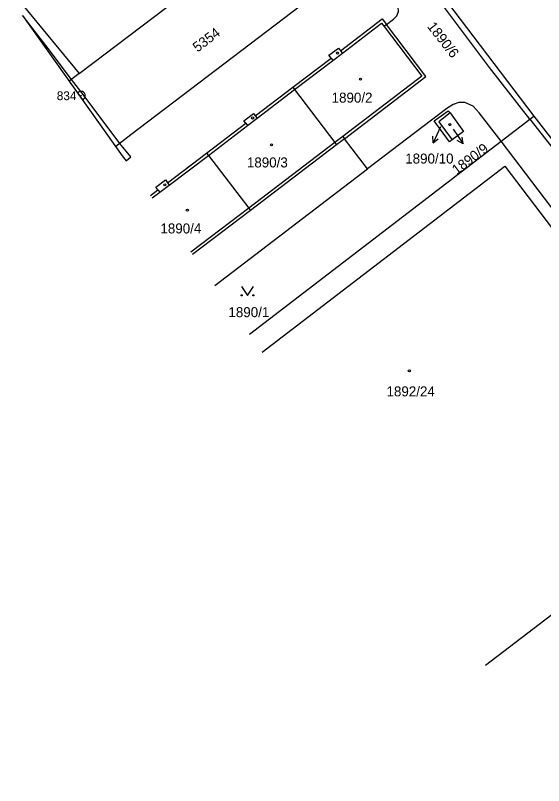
# Model space of a CAD drawing. Extents: x -821458 to -820266, y -1071458 to -1069826.
# Drawn here: x -821179.5 to -821089.7, y -1070873.1 to -1070742.2 of the extents above; entities that cross this region are included whole.
import ezdxf

# ---------------------------------------------------------------- set-up
doc = ezdxf.new("R2010")
doc.units = 0
for name, color, linetype in [('Vrstva 1', 7, 'Continuous'), ('Vrstva 13', 7, 'Continuous'), ('Vrstva 2', 7, 'Continuous'), ('Vrstva 3', 7, 'Continuous'), ('Vrstva 4', 7, 'Continuous'), ('Vrstva 5', 7, 'Continuous'), ('Vrstva 7', 7, 'Continuous'), ('Vrstva 8', 7, 'Continuous')]:
    doc.layers.add(name, color=color, linetype=linetype)

msp = doc.modelspace()

# ---------------------------------------------------------------- linework, layer by layer
at = {"layer": 'Vrstva 1'}
for p, q in [((-821168.67, -1070752.05), (-821145.53, -1070734.38)), ((-821179.52, -1070738.86), (-821168.67, -1070752.05)), ((-821168.67, -1070752.05), (-821170.38, -1070753.35)), ((-821096.91, -1070763.55), (-821092, -1070759.79)), ((-821092, -1070759.79), (-821091.35, -1070759.29)), ((-821091.35, -1070759.29), (-821086.06, -1070766.13)), ((-821139.72, -1070796.38), (-821096.91, -1070763.55)), ((-821123.55, -1070763.13), (-821124.88, -1070764.15)), ((-821124.88, -1070764.15), (-821139.54, -1070775.33)), ((-821139.54, -1070775.33), (-821149.39, -1070782.81))]:
    msp.add_line(p, q, dxfattribs=at)
for points in [[(-821057.85, -1070693.73), (-821110.68, -1070733.79), (-821091.35, -1070759.29)], [(-821092, -1070759.79), (-821098.88, -1070751), (-821112.32, -1070733.05), (-821111.78, -1070731.94), (-821111.85, -1070725.85)], [(-821123.75, -1070734.96), (-821159.87, -1070762.46), (-821162.46, -1070764.47)], [(-821116.4, -1070743.73), (-821115.21, -1070742.81), (-821114.66, -1070742.24), (-821114.37, -1070741.52), (-821114.39, -1070740.71), (-821114.75, -1070739.99), (-821116.84, -1070737.34), (-821123.75, -1070734.96)], [(-821132.34, -1070754.36), (-821125.83, -1070749.4), (-821126.18, -1070748.92), (-821124.56, -1070747.71), (-821124.2, -1070748.16), (-821117.15, -1070742.75), (-821116.4, -1070743.73)], [(-821123.55, -1070763.13), (-821109.68, -1070752.54), (-821116.4, -1070743.73)], [(-821147, -1070765.57), (-821140.34, -1070760.48), (-821140.68, -1070760.06), (-821139.04, -1070758.81), (-821138.72, -1070759.23), (-821132.34, -1070754.36)], [(-821132.34, -1070754.36), (-821132.03, -1070754.76), (-821125.19, -1070763.75), (-821124.88, -1070764.15)], [(-821096.91, -1070763.55), (-821100.61, -1070758.7), (-821101.64, -1070757.58), (-821103.05, -1070756.97), (-821104.08, -1070756.98), (-821105.06, -1070757.3), (-821106.12, -1070757.97), (-821119.65, -1070768.24), (-821123.55, -1070763.13)], [(-821105.24, -1070763.34), (-821105.67, -1070763.63), (-821108.27, -1070760.09), (-821105.91, -1070758.36), (-821105.57, -1070758.75)], [(-821105.57, -1070758.75), (-821107.48, -1070760.26), (-821105.24, -1070763.34)], [(-821105.57, -1070758.75), (-821103.27, -1070761.88), (-821105.24, -1070763.34)], [(-821085.02, -1070873.12), (-821066.67, -1070861.23), (-821045.28, -1070847.39), (-821043.79, -1070846.02), (-821042.61, -1070844.38), (-821041.71, -1070842.48), (-821041.39, -1070840.53), (-821041.49, -1070838.54), (-821041.98, -1070836.55), (-821042.62, -1070835.15), (-821043.18, -1070834.17), (-821055.9, -1070817.47), (-821096.91, -1070763.55)], [(-821156.52, -1070772.79), (-821155.27, -1070771.84), (-821155.65, -1070771.34), (-821154.01, -1070770.13), (-821153.64, -1070770.6), (-821147, -1070765.57)], [(-821147, -1070765.57), (-821146.7, -1070765.96), (-821139.84, -1070774.93), (-821139.54, -1070775.33)], [(-821137.57, -1070799.4), (-821096.27, -1070767.81), (-821077.16, -1070792.93), (-821076.94, -1070793.21), (-821084.09, -1070798.68), (-821081.35, -1070802.28), (-821074.19, -1070796.85), (-821056.57, -1070819.88), (-821099.56, -1070852.72)]]:
    msp.add_lwpolyline(points, dxfattribs=at)
at = {"layer": 'Vrstva 13'}
msp.add_line((-821178.33, -1070742.19), (-821161.35, -1070766.02), dxfattribs=at)
msp.add_lwpolyline([(-821161.35, -1070766.02), (-821160.67, -1070766.86), (-821159.91, -1070766.21), (-821161.76, -1070763.93), (-821167.98, -1070755.62), (-821169.98, -1070753.05), (-821173.97, -1070747.81), (-821178.05, -1070742.52), (-821178.33, -1070742.19)], dxfattribs=at)
at = {"layer": 'Vrstva 3'}
msp.add_lwpolyline([(-821141.04, -1070788.26), (-821140.04, -1070789.76), (-821139.04, -1070788.26)], dxfattribs=at)
for centre in [(-821141.04, -1070789.76), (-821139.04, -1070789.76)]:
    msp.add_circle(centre, 0.1, dxfattribs=at)
at = {"layer": 'Vrstva 4'}
for p, q in [((-821123.89, -1070748.55), (-821117.23, -1070743.48)), ((-821117.23, -1070743.48), (-821116.81, -1070744.04)), ((-821116.4, -1070743.73), (-821116.81, -1070744.04)), ((-821116.81, -1070744.04), (-821110.39, -1070752.47)), ((-821124.2, -1070748.16), (-821123.89, -1070748.55)), ((-821125.83, -1070749.4), (-821125.53, -1070749.81)), ((-821125.53, -1070749.81), (-821123.89, -1070748.55)), ((-821132.03, -1070754.76), (-821125.53, -1070749.81)), ((-821110.39, -1070752.47), (-821123.85, -1070762.73)), ((-821138.41, -1070759.63), (-821132.03, -1070754.76)), ((-821140.03, -1070760.87), (-821138.41, -1070759.63)), ((-821138.72, -1070759.23), (-821138.41, -1070759.63)), ((-821092, -1070759.79), (-821064.25, -1070795.28)), ((-821146.7, -1070765.96), (-821140.03, -1070760.87)), ((-821140.34, -1070760.48), (-821140.03, -1070760.87)), ((-821123.85, -1070762.73), (-821125.19, -1070763.75)), ((-821123.85, -1070762.73), (-821123.55, -1070763.13)), ((-821125.19, -1070763.75), (-821139.84, -1070774.93)), ((-821153.34, -1070771), (-821146.7, -1070765.96)), ((-821145.62, -1070788.1), (-821119.65, -1070768.24)), ((-821153.64, -1070770.6), (-821153.34, -1070771)), ((-821155.27, -1070771.84), (-821154.97, -1070772.24)), ((-821154.97, -1070772.24), (-821153.34, -1070771)), ((-821156.24, -1070773.2), (-821154.97, -1070772.24)), ((-821139.84, -1070774.93), (-821149.68, -1070782.4))]:
    msp.add_line(p, q, dxfattribs=at)
at = {"layer": 'Vrstva 5'}
for centre in [(-821124.73, -1070748.56), (-821120.8, -1070753), (-821139.17, -1070759.6), (-821105.62, -1070760.73), (-821135.94, -1070764.18), (-821154.11, -1070770.96), (-821150.27, -1070775.28), (-821112.51, -1070802.6)]:
    msp.add_circle(centre, 0.175, dxfattribs=at)
at = {"layer": 'Vrstva 7'}
for p, q in [((-821107.19, -1070761.12), (-821108.46, -1070763.84)), ((-821105.05, -1070761.48), (-821103.37, -1070763.97)), ((-821108.46, -1070763.84), (-821108.49, -1070762.72)), ((-821108.46, -1070763.84), (-821107.58, -1070763.14)), ((-821103.37, -1070763.97), (-821104.35, -1070763.42)), ((-821103.37, -1070763.97), (-821103.52, -1070762.86))]:
    msp.add_line(p, q, dxfattribs=at)
at = {"layer": 'Vrstva 8'}
msp.add_line((-821168.96, -1070755.34), (-821168.12, -1070756.52), dxfattribs=at)
msp.add_circle((-821168.38, -1070755.82), 0.03, dxfattribs=at)
msp.add_arc((-821168.38, -1070755.82), 0.75, 290.3714, 140.5783, dxfattribs=at)

# ---------------------------------------------------------------- texts
at = {"layer": 'Vrstva 2'}
for s, rotation, p in [('5354', 37, (-821148.55, -1070748.49)), ('1890/6', 308, (-821109.56, -1070744.07)), ('1890/9', 37, (-821104.46, -1070769.32))]:
    msp.add_text(s, height=1.7, rotation=rotation, dxfattribs=at).set_placement(p)
for s, p in [('1890/2', (-821125.73, -1070756.99)), ('1890/3', (-821140.14, -1070768.01)), ('1890/10', (-821113.21, -1070767.35)), ('1890/4', (-821154.85, -1070779.23)), ('1890/1', (-821143.28, -1070793.47)), ('1892/24', (-821116.39, -1070806.94))]:
    msp.add_text(s, height=1.7, dxfattribs=at).set_placement(p)
at = {"layer": 'Vrstva 8'}
msp.add_text('834', height=1.5, dxfattribs=at).set_placement((-821172.48, -1070756.57))

doc.saveas('drawing.dxf')
